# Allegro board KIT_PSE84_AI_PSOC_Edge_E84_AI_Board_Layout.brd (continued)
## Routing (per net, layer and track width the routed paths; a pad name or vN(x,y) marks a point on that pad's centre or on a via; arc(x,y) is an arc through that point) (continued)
AMIC2_CTB_REF: length 34.9
  TOP w0.089: v1(29.15,31.35) U1.J14
  L04_SIG2 w0.089: 31.17,31.71 29.51,31.71 v1(29.15,31.35)
  L04_SIG2 w0.157: 31.17,31.71 31.73,32.28 31.73,32.55 32.39,33.21 32.39,40.98 31.08,42.29 31.08,49.07 31.06,49.09 31.06,49.16 30.12,50.1 30.12,50.11 28.57,51.66 27.58,51.66 27.44,51.79 21.26,51.79 v2(20.4,50.93)
  BOTTOM w0.15: v2(20.4,50.93) 20.68,51.21 21.05,51.21 21.3,51.47 R228.1
AMIC_1V8: length 44
  TOP w0.229: v3(32.64,51.49) 32.94,51.79 C126.1 ; R224.2 R124.2 4.56,53.09 4.56,53.08 C118.1 4.17,54.42 4.18,54.43 v3(4.18,54.9)
  L03_SIG1 w0.229: v3(23.5,52.71) 22.73,51.94 21.03,51.94 20.85,51.77 13.89,51.77 12.65,53.01 v3(12.65,54.51)
  L04_SIG2 w0.229: v3(12.65,54.51) 11.52,54.51 11.12,54.9 v3(4.18,54.9) ; v3(32.64,51.49) 30.84,53.29 24.08,53.29 v3(23.5,52.71)
  BOTTOM w0.229: v3(12.65,54.51) 12.65,52.02 11.45,50.82 R125.1 ; v3(32.64,51.49) 32.33,51.8 U9.2 ; v3(23.5,52.71) 23.5,52.56 23.72,52.33 R134.1 ; U10.2 v3(4.18,54.9)
BOOT: length 36.6
  TOP w0.15: U1.N8 25.2,28.81 v1(25.2,28.79)
  L04_SIG2 w0.089: 30.28,39.29 30.86,38.71 31.17,38.71 ; 31.17,32.77 30.33,31.93 29.47,31.93 29.25,31.71 29.25,31.71 29.24,31.7 28.96,31.7 28.79,31.54 28.79,31.25 28.6,31.06 26.39,31.06 26.2,30.87 26.2,30.87 26.18,30.85 26.18,30.62 25.97,30.4 25.73,30.4 25.54,30.21 25.54,29.62 25.53,29.61 25.53,29.12 v1(25.2,28.79)
  L04_SIG2 w0.157: 30.28,39.29 30.04,39.53 30.04,45.91 v2(30.33,46.2) ; 31.17,32.77 31.42,33.02 31.57,33.02 32.13,33.59 32.13,38.31 31.73,38.71 31.17,38.71
  BOTTOM w0.15: R189.1 22.55,41.8 24.46,43.71 25.48,43.71 25.86,44.1 25.86,45.62 26.92,46.69 29.84,46.69 v2(30.33,46.2)
BT_DEV_WAKE: length 19
  TOP w0.15: v1(30.19,35.18) 29.66,35.18 U1.D15 ; U25.40 27.32,50.46 v2(27.3,50.47)
  L03_SIG1 w0.089: v1(30.19,35.18) 30.44,35.43 30.51,35.5 30.51,36.58 28.66,38.42 28.66,39.41
  L03_SIG1 w0.157: v2(27.3,50.47) 27.3,43.51 28.66,42.16 28.66,39.41
  BOTTOM w0.15: R106.2 27.31,50.04 27.3,50.04 v2(27.3,50.47)
BT_HOST_WAKE: length 22.4
  TOP w0.15: U25.41 26.82,50.26 v2(26.6,50.48) ; U1.D14 v1(29.12,35.29)
  L03_SIG1 w0.089: v1(29.12,35.29) 29.58,35.29 30.02,34.84 30.55,34.84 30.71,35 30.71,36.66 28.98,38.39 28.98,39.29
  L03_SIG1 w0.157: v2(26.6,50.48) 27.03,50.9 27.53,50.9 27.97,50.47 27.97,43.41 28.98,42.39 28.98,39.29
  BOTTOM w0.15: R107.2 27.2,51.08 v2(26.6,50.48)
BT_REG_ON: length 22.7
  TOP w0.15: U1.E14 v1(29.12,34.64) ; U25.8 20.84,45.69 20.72,45.8 R105.2 20,45.8 19.8,46 v2(19.48,46)
  L04_SIG2 w0.089: v1(29.12,34.64) 29.49,35.01 29.49,36.41 28.79,37.1 28.79,37.55 27.36,38.99 27.36,39.29
  L04_SIG2 w0.157: v2(19.48,46) 21.06,46 21.46,46.41 26.05,46.41 27.36,45.1 27.36,39.29
BT_UART_CTS_MCU_RTS: length 20.9
  TOP w0.15: U25.48 23.32,50.24 v2(22.89,50.67) ; U1.A14 v1(29.12,37.24)
  L03_SIG1 w0.089: 27.86,39.29 27.86,38.86 29.12,37.61 v1(29.12,37.24)
  L03_SIG1 w0.157: v2(22.89,50.67) 23.34,51.13 25.14,51.13 26.95,49.32 26.95,43.38 27.86,42.47 27.86,39.29
  BOTTOM w0.15: v2(22.89,50.67) 22.48,50.67 22.14,50.33 TP55.1
BT_UART_RTS_MCU_CTS: length 21.8
  TOP w0.15: U1.C15 30.02,35.61 v1(30.08,35.68) ; U25.47 23.82,50.52 23.67,50.67 v2(23.62,50.67)
  L04_SIG2 w0.089: 28.73,39.29 28.73,38.43 30.4,36.75 30.4,36 v1(30.08,35.68)
  L04_SIG2 w0.157: 28.73,39.29 28.73,42.01 28.07,42.67 28.07,48.34 26.9,49.51 24.79,49.51 v2(23.62,50.67)
  BOTTOM w0.15: TP56.1 23.39,50.45 v2(23.62,50.67)
BT_UART_RX_MCU_TX: length 17.9
  TOP w0.15: U1.A13 v1(28.47,37.24) ; U25.45 24.82,50.45 24.92,50.55 24.92,50.62 v2(24.94,50.65)
  L03_SIG1 w0.089: v1(28.47,37.24) 28.47,37.85 27.53,38.79 27.53,39.29
  L03_SIG1 w0.157: 27.53,39.29 27.53,42.04 25.68,43.89 25.68,49.91 v2(24.94,50.65)
  BOTTOM w0.15: v2(24.94,50.65) 25.55,50.65 25.91,50.29 TP53.1
BT_UART_TX_MCU_RX: length 20.7
  TOP w0.15: v2(24.32,50.7) U25.46 ; v1(30.02,36.53) 29.71,36.53 U1.B15
  L03_SIG1 w0.089: 27.2,39.29 27.2,38.63 27.49,38.34 27.49,37.1 27.68,36.91 27.99,36.91 28.14,36.75 28.14,36.45 28.33,36.26 29.76,36.26 v1(30.02,36.53)
  L03_SIG1 w0.157: v2(24.32,50.7) 24.32,44.54 27.2,41.66 27.2,39.29
  BOTTOM w0.15: v2(24.32,50.7) 24.65,50.37 TP54.1
DISP_VDD_3V3:
  vias: v3(16.99,57.71) v3(17.98,57.68)
DSI_CLK_N: length 37
  TOP w0.102: J10.11 9.37,56.62 9.74,56.99 9.74,59.71 v2(9.49,59.97)
  L03_SIG1 w0.102: v2(9.49,59.97) 9.73,59.73 9.73,58.68 8.51,57.45 8.51,57.08 8.83,56.75 8.83,56.61 8.69,56.46 8.55,56.46 8.22,56.79 7.84,56.79 7.53,56.48 7.53,56.1 7.86,55.77 7.86,55.63 7.72,55.49 7.57,55.49 7.24,55.81 6.87,55.81 6.58,55.52 6.58,52.23 8.13,50.68 8.13,44.25 11.89,40.49 14.54,40.49 14.76,40.7 15.3,40.7 v2(15.46,40.54)
  BOTTOM w0.102: v2(15.46,40.54) 15.62,40.69 16.2,40.69 16.62,40.28 18.17,40.28 R66.1
DSI_CLK_P: length 36.9
  TOP w0.102: J10.10 10.37,56.63 10,57.01 10,59.71 v2(10.26,59.97)
  L03_SIG1 w0.102: v2(15.46,41.31) 15.46,41.09 15.36,40.99 14.64,40.99 14.42,40.77 12.01,40.77 8.41,44.37 8.41,50.8 6.86,52.35 6.86,55.41 6.98,55.53 7.13,55.53 7.46,55.21 7.83,55.21 8.14,55.51 8.14,55.89 7.81,56.22 7.81,56.36 7.96,56.51 8.1,56.51 8.43,56.18 8.81,56.18 9.12,56.49 9.12,56.87 8.79,57.19 8.79,57.34 10.01,58.56 10.01,59.73 v2(10.26,59.97)
  BOTTOM w0.102: R67.1 18.17,40.53 16.72,40.53 16.31,40.95 15.57,40.95 15.46,41.05 v2(15.46,41.31)
DSI_DATA0_N: length 36.9
  TOP w0.102: v2(12.49,58.32) 12.64,58.32 12.74,58.21 12.74,57.91 12.59,57.76 12.59,57.45 12.74,57.3 12.74,56.99 12.37,56.62 J10.8
  L03_SIG1 w0.102: v2(12.49,58.32) 12.69,58.32 12.79,58.42 12.79,59.02 12.68,59.13 11.63,59.13 11.07,58.57 11.07,57.21 9.09,55.23 9.09,49.48 9.27,49.3 9.27,49 9.09,48.82 9.09,48.39 9.27,48.21 9.27,47.91 9.09,47.73 9.09,47.42 9.27,47.24 9.27,46.94 9.09,46.75 9.09,46.1 9.27,45.92 9.27,45.62 9.09,45.44 9.09,44.65 11.12,42.62 13.5,42.62 14.05,42.08 14.05,41.4 14.15,41.3 v2(14.36,41.3)
  BOTTOM w0.102: v2(14.36,41.3) 14.17,41.3 14.07,41.2 14.07,37.74 14.34,37.47 14.91,37.47 15.37,37.92 16.82,37.92 17.69,37.05 17.98,37.05 18.14,37.22 R70.1
DSI_DATA0_P: length 36.9
  TOP w0.102: v2(13.26,58.32) 13,58.06 13,56.98 13.37,56.61 J10.7
  L03_SIG1 w0.102: v2(13.26,58.32) 13.08,58.5 13.08,59.14 12.8,59.41 11.52,59.41 10.79,58.69 10.79,57.33 8.81,55.35 8.81,44.53 11,42.34 13.39,42.34 13.76,41.96 13.76,41.48 v2(13.59,41.3)
  BOTTOM w0.102: R71.1 17.87,36.8 17.58,36.8 16.71,37.67 15.47,37.67 15.01,37.21 14.24,37.21 13.82,37.63 13.82,41.07 v2(13.59,41.3)
DSI_DATA1_N: length 37
  TOP w0.102: v2(6.49,58.9) 6.64,58.9 6.74,58.8 6.74,58.5 6.59,58.34 6.59,58.04 6.74,57.89 6.74,57.01 6.37,56.64 J10.14
  L03_SIG1 w0.102: v2(6.49,58.9) 6.7,58.9 6.8,59.01 6.8,59.44 6.63,59.61 5.86,59.61 5.61,59.36 5.61,52.07 7.7,49.99 7.7,49.48 7.88,49.3 7.88,49 7.7,48.82 7.7,48.37 7.88,48.18 7.88,47.88 7.7,47.7 7.7,47.37 7.88,47.19 7.88,46.89 7.7,46.71 7.7,46.26 7.88,46.08 7.88,45.77 7.75,45.64 7.75,43.99 10.24,41.5 10.24,40.5 12.44,38.3 14.38,38.3 14.48,38.41 v2(14.48,38.64)
  BOTTOM w0.102: R68.1 18.17,38.8 17.69,38.8 17.27,38.38 15.18,38.38 15.1,38.3 14.58,38.3 14.48,38.41 v2(14.48,38.64)
DSI_DATA1_P: length 37
  TOP w0.102: v2(7.26,58.9) 7,58.65 7,56.99 7.37,56.61 J10.13
  L03_SIG1 w0.102: v2(7.26,58.9) 7.09,59.07 7.09,59.55 6.75,59.89 5.75,59.89 5.33,59.48 5.33,51.95 7.41,49.87 7.41,45.81 7.47,45.76 7.47,43.88 9.96,41.39 9.96,40.39 12.32,38.02 14.33,38.02 v2(14.48,37.87)
  BOTTOM w0.102: v2(14.48,37.87) 14.66,38.05 15.2,38.05 15.28,38.13 17.38,38.13 17.79,38.54 18.17,38.54 R69.1
ECO_IN: length 9.8
  TOP w0.15: v1(23.28,36.59) 23.34,36.53 23.34,36.52 U1.B6 ; v2(21.71,38.9) 21.11,38.9 20.72,39.3 20.72,39.46 20.12,40.06 20.12,40.1 ; 20.12,40.1 20.88,40.1 21.4,39.58 Y1.1 ; 20.12,40.1 C55.1
  L03_SIG1 w0.089: 24.28,37.14 24.24,37.11 24.24,37.1 24.05,36.91 23.6,36.91 23.52,36.84 23.52,36.83 v1(23.28,36.59)
  L03_SIG1 w0.157: 24.28,37.14 24.28,38.53 23.63,39.19 22,39.19 v2(21.71,38.9)
ECO_OUT: length 9.2
  TOP w0.15: v2(24.66,40.44) 24.6,40.38 C56.1 23.75,40.38 23.55,40.58 Y1.3 ; U1.F8 v1(25.22,33.99)
  L03_SIG1 w0.157: v1(25.22,33.99) 24.59,34.62 24.59,39.96 24.66,40.03 v2(24.66,40.44)
EXT_CLK: length 7.2
  TOP w0.15: U1.P4 21.94,28.11 v1(21.93,28.11)
  L03_SIG1 w0.089: v2(19.66,30.38) 19.66,30.38 20.14,29.9 20.14,29.39 20.47,29.06 21.13,29.06 21.18,29.11 21.45,29.11 21.64,28.92 21.64,28.47 21.69,28.43 21.69,28.35 v1(21.93,28.11)
  BOTTOM w0.15: v2(19.66,30.38) 19.66,32.32 19.34,32.65 R218.2
I2C_SCL_1V8: length 151.8
  TOP w0.089: U1.H7 24.53,32.07 v1(24.54,32.07) ; U18.13 19.1,20.96
  TOP w0.15: U6.4 35,18.99 v2(35.26,18.74) ; 19.1,20.96 19.1,20.8 18.75,20.46 18.75,20.44 18.5,20.19 R32.1 17.79,20.19 17.69,20.29 v2(16.98,20.29) ; v2(35.26,14.86) 35.2,14.86 34.61,15.45 34.51,15.45 U22.2
  L03_SIG1 w0.157: v2(35.26,14.86) 34.76,15.35 33.93,15.35 32.26,17.02 32.26,18.34 32.61,18.69 34.8,18.69 34.85,18.74 v2(35.26,18.74) ; v2(23.65,23.88) 23.22,23.45 23.22,13.94 22.36,13.08 22.36,13.08 20.56,11.28 19.9,11.28 19.9,11.28 19.2,11.28 18.19,12.29 17.35,12.29 16.64,13 15.87,13 15.44,12.58 8.46,12.58 v2(7.92,13.11) 8.21,13.4 8.34,13.4 9.54,14.6 9.54,15.52 10.06,16.03 10.06,19.98 10.89,20.8 15.88,20.8 16.39,20.29 v2(16.98,20.29) ; v2(10.03,24.45) 10.03,25.59 8.28,27.33 8.28,30.68 7.95,31.02 6.89,31.02 5.79,29.92 3.71,29.92 3.07,30.56 3.07,36.88 3.48,37.29 4.37,37.29 5.16,38.08 5.16,39.24 4.6,39.8 3.58,39.8 3.05,40.34 3.05,44.58 v2(3.71,45.24)
  L04_SIG2 w0.089: 24.64,27.82 24.64,30.65 24.91,30.92 24.91,31.7 v1(24.54,32.07)
  L04_SIG2 w0.102: 24.64,27.82 24.64,26.7 23.92,25.98 23.92,24.15 v2(23.65,23.88)
  L04_SIG2 w0.157: v2(35.26,18.74) 34.83,19.16 34.83,19.8 33.72,20.92 31.79,20.92 31.44,21.26 30.28,21.26 29.9,20.88 29.9,20.6 29.69,20.39 29.41,20.39 25.34,16.33 19.4,16.33 18.76,16.97 15.6,16.97 15.29,16.66 14.14,16.66 12.32,14.83 9.93,14.83 9.41,15.36 8.39,15.36 8.07,15.68 6.31,15.68 6.07,15.44 6.07,14.18 7.14,13.11 v2(7.92,13.11)
  BOTTOM w0.15: U28.10 10.14,24.66 10.06,24.57 10.06,24.49 v2(10.03,24.45) 10.03,24.09 11,23.12 13.46,23.12 14.1,22.48 14.1,21.29 15.09,20.29 v2(16.98,20.29) 16.98,19.88 17.02,19.85 17.02,19.84 17.88,18.97 19.41,18.97 19.74,18.64 U2.38 ; v2(3.71,45.24) 3.71,45.64 4.29,46.23 5.77,46.23 5.8,46.2 5.88,46.2 6.2,45.87 R223.2
I2C_SCL_3V3: length 105.5
  TOP w0.15: J14.17 3.1,24.39 3.1,29.08 3.71,29.69 4.6,29.69 5.21,30.3 5.21,44.82 4.42,45.6 4.42,47.27 5.13,47.98 5.13,48.68 10.53,54.08 14.83,54.08 15.37,54.62 J10.5 15.37,57.27 15.37,57.28 v2(15.37,57.71) ; v1(25.87,29.47) 25.84,29.47 U1.M9
  L03_SIG1 w0.157: v2(15.37,57.71) 15.9,57.18 20.13,57.18 21.31,56.01 v2(21.71,56.01)
  L04_SIG2 w0.089: 31.17,31.12 30.94,31.12 30.15,30.33 29.78,30.33 29.68,30.42 28.98,30.42 28.97,30.41 27.32,30.41 27.3,30.4 27.01,30.4 27,30.39 26.41,30.39 26.19,30.17 26.19,29.79 26.12,29.71 v1(25.87,29.47)
  L04_SIG2 w0.157: 31.17,31.12 31.99,31.94 31.99,32.44 32.65,33.1 32.65,41.09 31.34,42.4 31.34,49.18 31.32,49.2 31.32,49.26 30.38,50.21 30.38,50.22 28.37,52.22 22.67,52.22 22.05,52.85 22.05,55.67 v2(21.71,56.01)
  BOTTOM w0.15: v2(21.71,56.01) 21.31,55.6 20.27,55.6 20.12,55.75 R207.1 20.12,57.26 20.65,57.79 J7.4 ; v2(15.37,57.71) 15.37,56.97 13.97,55.58 9.32,55.58 8.43,54.69 J16.2
I2C_SDA_1V8: length 147.4
  TOP w0.089: U18.14 19.6,20.96
  TOP w0.15: v1(24.59,31.4) 24.59,31.4 U1.J8 ; 19.6,20.96 19.6,20.73 19.42,20.55 19.38,20.55 19.25,20.42 R31.1 19.67,20.19 20.61,19.25 v2(21.02,19.25) ; U22.1 34.51,14.65 34.83,14.65 v2(35.23,14.25) ; v2(35.24,19.39) 34.98,19.64 U6.3 ; v2(6.4,40.62) 5.61,41.4 5.61,44.77 4.73,45.65 4.73,46.33 v2(5.21,46.81)
  L03_SIG1 w0.089: 21.47,32.98 22.26,32.98 22.41,32.83 22.83,32.83 22.87,32.88 22.87,32.88 23.11,33.11 23.39,33.11 23.62,32.88 23.62,32.56 23.56,32.5 23.56,31.89 23.75,31.71 24.28,31.71 v1(24.59,31.4) ; v2(15.98,45.31) 15.98,45.31
  L03_SIG1 w0.152: 15.98,45.31 16.03,45.31 16.39,44.96 16.54,44.96 18.71,42.79 18.71,35.44 21.17,32.98 21.47,32.98
  L03_SIG1 w0.157: v2(8.86,13.18) 9.8,14.12 9.8,15.41 11.51,17.11 11.51,19.74 12.24,20.47 15.82,20.47 16.42,19.88 17.12,19.88 17.17,19.92 20.34,19.92 v2(21.02,19.25) ; v2(35.23,14.25) 34.54,14.94 32.82,14.94 31.8,15.95 31.8,18.95 32.33,19.48 33.34,19.48 33.82,19 34.86,19 v2(35.24,19.39) ; v2(6.4,40.62) 6.4,33.07 6.93,32.54 7.59,32.54 9.45,30.68 9.45,27.36 10.51,26.29 v2(10.51,24.18)
  L04_SIG2 w0.157: v2(8.86,13.18) 8.26,12.57 7.16,12.57 5.81,13.93 5.81,15.54 6.2,15.93 8.25,15.93 8.53,15.65 10.31,15.65 10.59,15.37 11.77,15.37 13.52,17.12 14.63,17.12 14.89,17.38 15.61,17.38 15.76,17.23 25.71,17.23 28.62,20.14 28.62,20.83 28.98,21.18 29.83,21.18 30.17,21.52 31.55,21.52 31.89,21.18 34.04,21.18 35.24,19.98 v2(35.24,19.39)
  BOTTOM w0.15: v2(15.98,45.31) 15.37,45.31 15.06,45.01 15.06,44.1 12.7,41.73 7.52,41.73 v2(6.4,40.62) ; R220.2 5.46,46.91 5.36,46.81 v2(5.21,46.81) ; v2(21.02,19.25) 21.03,19.24 21.03,19.19 20.88,19.04 U2.39 19.72,19.04 19.69,19.08 19.68,19.08 19.43,19.33 17.91,19.33 17.39,19.85 17.39,20.46 17.15,20.69 15.12,20.69 14.38,21.44 14.38,22.79 13.79,23.37 11.32,23.37 v2(10.51,24.18) 10.59,24.26 10.59,24.38 10.64,24.43 U28.9
I2C_SDA_3V3: length 101.7
  TOP w0.15: v1(25.86,27.53) 25.82,27.53 U1.R9 ; v2(16.32,57.75) 16.32,57.34 16.37,57.29 J10.4 16.37,55.2 15,53.83 10.77,53.83 5.71,48.77 5.71,46.41 v2(5.13,45.82)
  L03_SIG1 w0.157: v2(21.59,55.17) 22,55.17 22.2,55.37 22.2,56.34 20.32,58.22 16.79,58.22 v2(16.32,57.75)
  L04_SIG2 w0.089: v1(25.86,27.53) 25.98,27.53 26.33,27.19 26.33,26.87 25.96,26.49 25.96,25.66
  L04_SIG2 w0.102: 25.3,23.77 25.3,24.03 25.96,24.69 25.96,25.66
  L04_SIG2 w0.157: v2(4.67,19.38) 5.8,18.25 6.2,18.25 6.2,18.25 11.24,18.25 11.89,18.9 12.98,18.9 14.21,20.13 16.18,20.13 16.83,19.49 19.72,19.49 20.33,18.87 21.56,18.87 23.19,20.5 23.19,21.08 24.63,22.52 24.63,23.11 25.3,23.77
  BOTTOM w0.15: v2(5.13,45.82) 5.61,45.34 5.61,40.49 4.93,39.8 3.56,39.8 2.92,39.17 2.92,24.71 J14.18 3.16,21.78 3.16,20.43 4.22,19.38 v2(4.67,19.38) ; J16.4 10.97,54.69 11.53,55.25 14.22,55.25 16.32,57.34 v2(16.32,57.75) ; J7.3 19.65,57.19 19.47,57.02 R206.1 19.47,55.61 19.91,55.17 v2(21.59,55.17)
I2S_TX_FSYNC: length 32.5
  TOP w0.15: U1.E5 22.63,34.62 v1(22.61,34.62)
  L03_SIG1 w0.089: v1(22.61,34.62) 22.44,34.78 22.41,34.78 22.23,34.96 21.83,34.96 21.64,35.15 21.64,35.42 21.63,35.43 21.63,36.16 21.5,36.29 20.83,36.29 20.61,36.07 19.9,36.07
  L03_SIG1 w0.157: v2(20.31,37.63) 19.93,37.63 19.59,37.28 19.59,36.38 19.9,36.07
  L04_SIG2 w0.089: v2(20.31,37.63) 19.69,37.01 19.25,37.01 18.72,36.48
  L04_SIG2 w0.157: 18.72,36.48 16.66,34.42 16.3,34.42 14.83,32.94 14.83,32.64 14.32,32.13 12.52,32.13 10.8,30.41 10.8,24.47 10.92,24.35 10.92,23.62 11.1,23.45 12.69,23.45 12.9,23.66 v2(12.9,24.33)
  BOTTOM w0.15: U28.6 11.87,26.78 12.02,26.63 12.02,25.37 12.9,24.49 v2(12.9,24.33)
I2S_TX_MCK: length 32.5
  TOP w0.15: U1.D4 v1(21.97,35.29)
  L04_SIG2 w0.089: 20.55,35.61 21.45,35.61 21.47,35.6 21.66,35.6 v1(21.97,35.29)
  L04_SIG2 w0.157: v2(12.43,24.04) 11.8,24.04 11.63,24.21 11.63,24.66 11.48,24.82 11.44,24.82 11.28,24.98 11.28,25.29 11.44,25.45 11.86,25.45 12.02,25.61 12.02,25.85 11.78,26.08 11.34,26.08 11.18,26.24 11.18,26.55 11.34,26.71 11.83,26.71 12.12,26.99 12.12,28.15 11.42,28.85 11.42,29.1 11.61,29.28 11.9,29.28 12.52,28.67 12.74,28.67 13.14,29.06 13.14,29.28 12.21,30.21 12.21,30.43 12.43,30.66 12.66,30.66 13.58,29.73 13.8,29.73 14.92,30.84 15.94,30.84 16.18,31.09 16.18,31.5 16.96,32.28 16.96,32.5 16.72,32.75 16.72,32.97 16.94,33.2 17.16,33.2 17.43,32.92 17.73,32.92 17.96,33.14 17.96,33.37 17.54,33.78 17.54,34 17.74,34.2 17.96,34.2 18.35,33.81 18.62,33.81 19.58,34.77 19.58,34.99 19.04,35.53 19.04,35.76 19.2,35.92 19.42,35.92 19.96,35.38 20.19,35.38 20.42,35.61 20.55,35.61
  BOTTOM w0.15: v2(12.43,24.04) 12.02,24.04 12.01,24.05 11.47,24.05 11.23,24.29 11.23,25.72 U28.8
I2S_TX_SCK: length 32.5
  TOP w0.089: v1(23.95,30.74) 23.95,30.77 U1.K7
  L04_SIG2 w0.089: 18.72,31.3 18.86,31.44 19.09,31.44 19.26,31.26 19.26,31.16 19.46,30.96 19.96,30.96 20.21,30.71 20.21,29.93 20.37,29.77 20.69,29.77 20.84,29.93 20.84,30.8 21.01,30.96 22.94,30.96 23.01,31.04 23.65,31.04 v1(23.95,30.74)
  L04_SIG2 w0.157: 18.72,31.3 18.63,31.2 18.63,30.42 17.78,29.57 16.49,29.57 15.83,28.91 15.57,28.91 15.14,28.47 15.14,27.89 15.55,27.48 16.71,27.48 16.97,27.23 16.97,26.73 16.81,26.57 16.53,26.57 16.37,26.41 16.37,23.9 16.14,23.67 14.88,23.67 14.57,23.98 14.57,25.55 14.72,25.7 14.96,25.7 15.11,25.86 15.11,26.15 14.93,26.33 14.62,26.33 14.44,26.52 14.44,27.07 14.28,27.23 13.97,27.23 13.81,27.07 13.81,24.92 13.63,24.74 12.38,24.74 v2(12.22,24.58)
  BOTTOM w0.15: U28.7 11.47,26.28 11.76,25.99 11.76,25.96 11.77,25.95 11.77,25.03 11.93,24.87 11.93,24.86 v2(12.22,24.58)
I2S_TX_SD: length 32.6
  TOP w0.15: U1.E4 v1(21.97,34.64)
  L04_SIG2 w0.089: v1(21.97,34.64) 21.64,34.96 20.84,34.96 20.84,34.96
  L04_SIG2 w0.157: 20.84,34.96 20.68,34.96 19.99,34.26 19.99,34.04 20.91,33.12 20.91,32.95 20.62,32.67 20.42,32.67 19.4,33.68 19.18,33.68 19.03,33.53 19.03,33.22 20.47,31.78 20.47,31.45 20.31,31.29 19.97,31.29 18.53,32.73 18.31,32.73 18.08,32.5 18.08,31.79 17.9,31.6 17.68,31.6 17.3,31.98 17.07,31.98 16.85,31.76 16.85,31.54 17.23,31.16 17.23,30.93 16.81,30.51 16.81,30.25 16.58,30.03 16.36,30.03 16.1,30.29 15.88,30.29 15.4,29.82 15.18,29.82 14.83,30.17 14.61,30.17 14.39,29.94 14.39,29.72 15.03,29.08 15.03,28.86 14.82,28.65 14.57,28.65 13.94,29.28 13.72,29.28 13.49,29.05 13.49,28.83 14.12,28.2 14.12,27.98 13.9,27.76 13.68,27.76 13.05,28.38 12.83,28.38 12.48,28.04 12.48,27.61 12.64,27.45 12.92,27.45 13.08,27.29 13.08,26.98 12.92,26.82 12.64,26.82 12.48,26.66 v2(12.48,25.58)
  BOTTOM w0.15: v2(12.48,25.58) 12.48,25.66 12.29,25.85 12.29,26.8 11.81,27.28 U28.5
I3C_SCL: length 26.5
  TOP w0.15: U1.M4 21.97,29.44 21.92,29.44 v1(21.92,29.44)
  L03_SIG1 w0.089: 20.93,30.39 20.93,29.9 21.07,29.76 21.6,29.76 v1(21.92,29.44)
  L03_SIG1 w0.157: 20.93,30.39 16.74,34.58 16.74,37.24 15.38,38.6 15.38,39.51 15.89,40.02 15.89,41.46 14.14,43.21 11.05,43.21 10.1,44.16 10.1,44.87 v2(9.81,45.15)
  BOTTOM w0.15: v2(9.81,45.15) 9.81,45.9 TP71.1 9.25,45.9 9.15,45.8 R205.2 R222.2
I3C_SDA: length 27.6
  TOP w0.15: U1.L6 v1(23.27,30.09)
  L03_SIG1 w0.089: v1(23.27,30.09) 23.27,30.1 22.61,30.76 21.44,30.76 20.79,31.41 20.79,31.71
  L03_SIG1 w0.157: 20.79,31.71 20.26,32.24 19.96,32.24 18.63,33.57 18.61,33.57 17.29,34.89 17.29,38.33 16.23,39.39 16.23,41.5 14.22,43.51 11.11,43.51 10.36,44.26 v2(10.36,45.21)
  BOTTOM w0.15: v2(10.36,45.21) 10.36,46.48 TP72.1 9.58,47.04 9.45,46.91 R204.2 R221.2
IMU_INT1: length 11.9
  TOP w0.15: U1.L5 22.61,30.07 v1(22.61,30.05) ; v2(22.45,23.87) 21.82,23.87 20.92,22.98 U18.4
  L04_SIG2 w0.089: v1(22.61,30.05) 22.9,29.76 23.41,29.76 23.59,29.57 23.59,29.3 23.78,29.11 24.12,29.11 24.27,28.96 24.27,28.37
  L04_SIG2 w0.102: 24.27,28.37 24.27,27.91 24.16,27.8 23.05,27.8 22.78,27.53 22.78,25.77 22.99,25.56 22.99,24.41 v2(22.45,23.87)
IMU_INT2: length 8.6
  TOP w0.15: U18.9 18.39,22.48 18.42,22.51 18.51,22.51 v2(18.56,22.55) ; U1.P5 v1(22.62,28.14)
  L03_SIG1 w0.089: v1(22.62,28.14) 22.62,27.35 21.86,26.59
  L03_SIG1 w0.157: 21.86,26.59 20.96,25.69 20.96,24.72 20.88,24.64 20.88,24.63 19.19,22.94 19.06,22.94 19.06,22.94 18.94,22.94 v2(18.56,22.55)
JTAG_SEL: length 1.7
  TOP w0.15: U25.57 22.36,45.69 v2(22.04,46)
  BOTTOM w0.15: v2(22.04,46) 22.45,46 22.58,46.13 R110.2
KP_USB_DM: length 20.4
  TOP w0.114: J1.A7 25.91,5.97 25.81,5.86 25.81,5.3 v2(26.03,5.07) ; J1.B7 v2(24.91,7.74)
  L03_SIG1 w0.114: 25.42,7.74 25.54,7.86 25.54,8.44 27.78,10.69 27.78,12.53 v2(27.53,12.78) ; 25.42,7.74 25.54,7.63 25.54,6.89 24.65,6 24.65,5.49 24.46,5.3 24.46,4.36 24.72,4.1 25.53,4.1 25.83,4.4 25.83,4.87 v2(26.03,5.07) ; 25.42,7.74 v2(24.91,7.74)
  BOTTOM w0.114: U19.1 25.29,7.05 25.54,7.3 25.54,7.61 25.43,7.72 24.93,7.72 v2(24.91,7.74) ; R28.1 26.14,14.04 26.14,13.33 26.39,13.08 27.29,13.08 27.37,13.16 27.65,13.16 27.79,13.03 v2(27.53,12.78)
KP_USB_DP: length 20.3
  TOP w0.114: J1.B6 v2(26.41,7.74) ; J1.A6 25.41,5.97 25.58,5.8 25.58,5.21 25.43,5.07 v2(25.29,5.07)
  L03_SIG1 w0.114: v2(25.29,5.07) 25.47,5.07 25.58,4.96 25.58,4.5 25.42,4.34 24.82,4.34 24.71,4.46 24.71,5.2 24.89,5.39 24.89,5.9 25.12,6.12 25.28,6.12 25.38,6.01 25.55,6.01 25.71,6.18 25.71,6.34 25.6,6.44 25.6,6.6 25.79,6.79 25.79,7.63 25.9,7.74 ; 25.9,7.74 25.79,7.86 25.79,8.34 28.03,10.58 28.03,12.53 v2(28.27,12.78) ; 25.9,7.74 v2(26.41,7.74)
  BOTTOM w0.114: v2(28.27,12.78) 28.02,13.03 28.02,13.12 27.75,13.39 27.28,13.39 27.2,13.31 26.49,13.31 26.37,13.42 26.37,14.04 R26.1 ; v2(26.41,7.74) 26.38,7.77 25.88,7.77 25.77,7.66 25.77,7.33 U19.2
KP_VBUS:
  vias: v3(22.74,7.93) v3(23.27,7.63) v3(23.67,3.94) v3(23.67,2.67) v3(28.12,8.36) v3(28.07,7.68)
LPO_OUT_2FY: length 1.8
  TOP w0.15: R182.2 28.71,45.45 28.45,45.19 U25.30
MAG_INT: length 5.9
  TOP w0.15: U20.A1 18.42,27.66 19.97,27.66 20.63,27 22.13,27 U1.R5
MCU_UART_RX_KP3_TX: length 51.8
  TOP w0.15: U1.R2 v1(20.67,27.49)
  L03_SIG1 w0.089: v1(20.67,27.49) 20.67,27.14 20.02,26.49
  L03_SIG1 w0.102: 20.02,26.49 19.86,26.33
  L03_SIG1 w0.157: v2(6.99,14.94) 8.53,16.49 8.97,16.49 9.7,17.22 9.7,20.44 12.25,22.99 15.46,22.99 16.76,24.28 19.43,24.28 20.11,24.96 20.11,25.65 19.86,25.89 19.86,26.33
  L04_SIG2 w0.157: v2(28.97,13.62) 28.97,14.02 28.96,14.04 28.96,14.17 27.66,15.47 19.88,15.47 18.66,16.69 16.11,16.69 15.29,15.88 14.02,15.88 12.67,14.52 7.4,14.52 v2(6.99,14.94)
  BOTTOM w0.15: U2.20 26.65,16.12 27.4,15.37 28.24,15.37 28.42,15.19 28.42,14.51 28.96,13.97 28.96,13.67 28.97,13.65 v2(28.97,13.62)
MCU_UART_TX_KP3_RX: length 51.7
  TOP w0.15: U1.P2 v1(20.67,28.14)
  L03_SIG1 w0.089: v1(20.67,28.14) 20.09,27.56 20.04,27.56 20.02,27.53 19.18,27.53 18.98,27.33 18.98,27.04 19.15,26.87 19.15,26.59
  L03_SIG1 w0.157: v2(6.48,15.27) 8.36,17.15 8.36,18.53 8.13,18.76 8.13,19.69 9.12,20.68 9.12,21.9 10.52,23.29 13.92,23.29 15.59,24.96 16.47,24.96 16.76,25.25 18.23,25.25 18.23,25.25 19.05,25.25 19.48,25.68 19.48,26.23 19.23,26.49 19.23,26.52 19.15,26.59
  L04_SIG2 w0.157: v2(6.48,15.27) 6.48,14.86 7.07,14.26 13.86,14.26 15.21,15.62 15.4,15.62 16.22,16.43 18.56,16.43 19.78,15.22 27,15.22 27.61,14.61 v2(27.61,13.89)
  BOTTOM w0.15: v2(27.61,13.89) 27.61,14.3 27.41,14.5 R29.1 27.09,15.18 27.09,15.28 26.25,16.12 U2.21
MCU_VDD_3V3: length 25.7
  TOP w0.15: U1.R10 26.51,27.5 v1(26.51,27.49) ; U1.B11 v1(27.17,36.59) ; U1.D10 v1(26.52,35.29)
  TOP w0.229: R197.1 25.03,24.94 C179.1 C180.1 26.31,24.94 26.57,25.19 26.57,26.94 26.51,27 v1(26.51,27.49)
  L05_PWR w0.089: 31.17,36.09 31.08,36.09 30.26,36.91 27.49,36.91 v1(27.17,36.59) U1.B11 26.84,35.61 v1(26.52,35.29) 26.84,34.96 27.3,34.96 27.49,34.77 27.49,34.5 27.3,34.31 27.08,34.31 27.08,34.31 27.03,34.31 26.8,34.07 26.8,32.77 26.22,32.19 26.22,30.89 26.19,30.87 26.19,29.3 26.38,29.11 27.41,29.11 27.5,29.02 27.5,28.01 27.3,27.81 27.28,27.81 27.28,27.81 26.83,27.81 v1(26.51,27.49)
  L05_PWR w0.229: v3(31.55,36.09) 31.17,36.09
  BOTTOM w0.229: v1(26.51,27.49) 26.51,27 26.52,26.99 26.52,26.7 26.56,26.65 R154.2 ; C139.1 31.12,36.4 31.42,36.09 v3(31.55,36.09)
MEMORY_RST: length 17.9
  TOP w0.15: v1(13.23,37.03) 12.93,37.03 U3.A4 ; v1(23.27,30.67) 23.26,30.68 23.26,30.75 U1.K5
  BOTTOM w0.15: v1(23.27,30.67) 22.89,30.67 22.67,30.46 21.01,30.46 20.27,29.72 19.4,29.72 19,30.11 19,30.65 18.01,31.65 18.01,34.24 17.83,34.42 17.83,36.27 17.58,36.52 R208.1 16.69,36.52 16.36,36.86 15.9,36.86 15.51,36.47 13.75,36.47 13.23,36.98 v1(13.23,37.03)
Net_4: length 0.5
  TOP w0.15: 25.54,33.66 25.57,33.66 v1(25.89,33.99)
P5LP1_2: length 13.8
  TOP w0.15: v2(29.16,18.89) 29.48,18.89 29.95,18.42 30.57,18.42 v2(30.9,18.08)
  BOTTOM w0.15: v2(29.16,18.89) 29,19.04 U2.13 ; v2(30.9,18.08) 30.9,17.46 31.11,17.25 31.11,15.92 30.86,15.68 30.86,14.6 31.06,14.4 31.06,12.82 31.41,12.47 SW3.1 SW3.2
P5LP1_4: length 16.4
  TOP w0.15: R30.2 31.79,5.68 31.55,5.92 v2(31.55,6.2)
  L03_SIG1 w0.157: v2(29.06,17.93) 28.22,17.09 28.22,15.62 30.53,13.31 30.53,11.76 31.9,10.39 31.9,9.05 31.9,9.05 31.9,7.65 32.5,7.05 32.5,6.73 32.26,6.49 31.84,6.49 v2(31.55,6.2)
  BOTTOM w0.15: U2.15 28.75,18.24 v2(29.06,17.93)
P5LP_SIO_VREF: length 2.5
  BOTTOM w0.15: R21.2 R22.2 19.2,23.25 19.8,22.64 U2.48
P5LP_SWCLK: length 2.5
  BOTTOM w0.15: TP19.1 29.78,18.89 29.22,19.44 U2.12
P5LP_SWDIO: length 3.5
  BOTTOM w0.15: TP20.1 30.87,19.33 30.28,19.91 29.09,19.91 29.02,19.84 U2.11
P5LP_VCCD: length 19
  L03_SIG1 w0.229: v3(22.35,13.69) 22.35,13.98 22.71,14.33 22.71,18.79 22.3,19.2 22.3,20.98 22.05,21.24 22.05,24.47 22.17,24.6 22.17,24.63 22.56,25.02 v3(22.56,25.49)
  BOTTOM w0.178: U2.26 24.25,16.02 23.83,15.6 C44.1 23.83,14.81 23.68,14.66 23.27,14.66 22.88,14.27 22.88,13.99 22.58,13.69 v3(22.35,13.69) ; v3(22.56,25.49) 22.56,25.81 22.84,26.09 C45.1 23.07,25.72 23.05,25.7 U2.57
P5LP_VDD: length 39
  TOP w0.229: R18.1 29.61,8.79 29.97,9.15 30.22,9.15 v3(30.23,9.14)
  L04_SIG2 w0.229: v3(17.1,21.87) 17.42,21.87 17.9,21.4 19.34,21.4 20.22,22.27 20.22,24.79 v3(19.71,25.3)
  BOTTOM w0.157: C46.1 20.79,26.43 21.01,26.65 21.49,26.65 21.77,26.93 23.06,26.93 23.17,27.04 23.34,27.04 23.47,27.16 v3(23.75,27.16)
  BOTTOM w0.178: U2.24 25.05,15.6 25.1,15.54 C40.1 C39.1 ; U2.59 23.85,25.4 24.08,25.63 24.08,25.82 24.32,26.07 C49.1 24.32,26.49 24.31,26.51 C48.1 24.06,27.15 23.77,27.15 v3(23.75,27.16) ; v3(29.43,25.74) 29.11,26.06 28.92,26.06 28.9,26.04 C51.1 C50.1 27.22,26.04 27.05,25.86 U2.67 ; U2.52 21.05,25.19 20.79,25.44 C46.1 ; v3(18.64,18.54) 18.2,18.54 18.17,18.52 18.16,18.52 17.98,18.34 C37.1 C38.1 19.18,17.98 19.72,17.44 U2.35 ; U2.44 19.33,21.04 19.18,21.2 C36.1 C35.1 18.02,21.54 17.68,21.87 v3(17.1,21.87) ; U2.17 29.09,17.44 29.28,17.26 C42.1 C41.1 29.62,15.86 29.61,15.85 v3(29.61,15.81)
  BOTTOM w0.229: R25.1 28.92,14.71 29.56,14.07 30.09,14.07 v3(30.42,14.4) ; v3(19.71,25.3) 20.08,25.68 C47.1 20.09,26.07 C46.1 ; v3(29.43,25.74) 29.46,25.71 TP16.1
  BOTTOM w0.254: v3(25.2,12.8) 25.2,13.29 25.33,13.41 25.33,14.13 25.1,14.35 C39.1
P5LP_XRES: length 3.8
  BOTTOM w0.15: TP18.1 30.95,21.4 30.95,20.57 30.59,20.2 29.07,20.2 29.03,20.24 U2.10
P11_1: length 37.4
  TOP w0.15: U1.E11 v1(27.17,34.64)
  L03_SIG1 w0.089: 26.34,39.29 26.31,39.27 26.31,37.49 26.19,37.37 26.19,37.1 26.39,36.91 26.65,36.91 26.84,36.72 26.84,34.96 v1(27.17,34.64)
  L03_SIG1 w0.157: v2(12.75,45.55) 12.75,47.11 14.07,48.43 19.1,48.43 21.69,45.85 21.69,44.71 22.94,43.46 24.36,43.46 26.34,41.48 26.34,39.29
  BOTTOM w0.15: TP70.1 11.54,43.94 12.75,45.14 v2(12.75,45.55) 13.03,45.84 13.03,47.75 13.71,48.43 U40.7
P11_1_IN_3V3: length 29.1
  BOTTOM w0.15: J14.13 5.07,29.4 5.07,38.64 5.91,39.48 5.91,40.76 7.21,42.06 12.6,42.06 14.81,44.27 14.81,44.98 14.81,44.99 14.81,45.11 15.26,45.57 15.66,45.57 15.81,45.72 16.15,45.72 16.39,45.96 16.39,48.33 16.28,48.43 U40.2
P16_0: length 59.9
  TOP w0.15: U1.M11 v1(27.17,29.44) ; J14.6 0.58,37.62 0.58,20.14 v2(1.58,19.14)
  L04_SIG2 w0.089: v1(27.17,29.44) 27.5,29.1 27.5,28.25 28.19,27.56 28.19,26.62 28.17,26.59
  L04_SIG2 w0.157: 28.17,26.59 28.09,26.51 28.09,25.25 27.5,24.67 27.5,24.17 27.83,23.84 27.83,23.54 27.71,23.43 27.71,20.77 24.68,17.75 15.98,17.75 15.48,18.24 13.87,18.24 12.73,17.1 11.23,17.1 10.84,16.7 3.51,16.7 1.58,18.62 v2(1.58,19.14)
P16_1: length 106
  TOP w0.15: v1(28.55,27.36) 28.55,27.4 U1.R13
  L03_SIG1 w0.089: 29.53,26.59 29.53,26.82 28.99,27.36 v1(28.55,27.36)
  L03_SIG1 w0.157: J14.5 2.72,40.01 2.72,41.81 2.31,42.22 0.91,42.22 0.59,41.89 0.59,9.96 3.28,7.27 3.28,5.26 5.34,3.2 6.02,3.2 8.64,0.59 27.3,0.59 31.46,4.75 33.75,4.75 34.67,5.67 34.67,8.97 34.24,9.4 34.24,9.7 33.84,10.11 33.84,10.13 32.13,11.83 32.13,13.29 30.58,14.83 30.25,14.83 30.02,15.07 30.02,18.9 29.63,19.29 29.63,19.65 30.15,20.17 30.56,20.17 30.94,20.55 30.94,21.12 30.48,21.58 30.48,23.53 30.26,23.75 30.26,25.87 29.53,26.59
P16_2: length 51.6
  TOP w0.15: U1.N11 v1(27.17,28.79)
  L04_SIG2 w0.089: v1(27.17,28.79) 26.84,28.46 26.38,28.46 26.19,28.27 26.19,28 26.38,27.81 26.64,27.81 26.83,27.62 26.83,26.92 26.19,26.27 26.19,24.08 26.12,24.01 26.12,23.46
  L04_SIG2 w0.157: J14.8 2.9,34.74 2.9,20.49 5.4,17.99 6.09,17.99 6.09,17.99 11.35,17.99 11.97,18.62 13.06,18.62 14.31,19.87 16.07,19.87 16.72,19.23 19.61,19.23 20.27,18.57 22.49,18.57 23.65,19.72 23.65,20.99 26.12,23.46
P16_3: length 64
  TOP w0.15: v1(27.15,30.06) 27.15,30.1 U1.L11
  L04_SIG2 w0.089: v1(27.15,30.06) 27.19,30.06 27.54,29.71 27.97,29.71 28.16,29.52 28.16,28.95 28.15,28.95 28.15,28.63 28.16,28.62 28.16,27.97 28.36,27.77 28.59,27.77 28.87,27.49 28.87,26.79 28.73,26.65 28.73,26.59
  L04_SIG2 w0.157: 28.73,26.59 28.52,26.39 28.52,24.6 28.17,24.25 28.17,20.78 24.88,17.49 15.87,17.49 15.38,17.98 14.01,17.98 12.87,16.84 11.34,16.84 10.94,16.44 2.79,16.44 0.59,18.64 0.59,36.68 0.99,37.09 3.1,37.09 J14.7
P16_4: length 50.1
  TOP w0.15: U1.P11 v1(27.17,28.14)
  L04_SIG2 w0.089: v1(27.17,28.14) 27.53,27.77 27.53,26.24
  L04_SIG2 w0.102: 27.53,26.24 27.1,25.81
  L04_SIG2 w0.157: J14.10 2.64,32.46 2.64,30.81 2.63,30.8 2.63,19.09 4.76,16.96 10.73,16.96 11.15,17.37 12.64,17.37 13.76,18.5 15.59,18.5 16.08,18 23.85,18 27.08,21.24 27.08,25.78 27.1,25.81
P16_5: length 95.6
  TOP w0.15: v1(26.54,30.06) U1.L10 ; J14.9 2.82,32.23 2.82,20.37 3.81,19.38 3.81,14.81 3.43,14.43 v2(1.04,14.43)
  L03_SIG1 w0.089: v1(26.54,30.06) 26.84,29.76 26.84,29.3 27.03,29.11 27.3,29.11 27.49,28.92 27.49,28.52 27.8,28.21 27.8,27.82 28.21,27.41 28.21,27.21 28.83,26.59
  L03_SIG1 w0.157: v2(1.04,14.43) 0.91,14.3 0.91,10.2 3.63,7.48 3.63,5.27 5.45,3.46 6.13,3.46 8.75,0.85 27.19,0.85 31.35,5 31.7,5 32.88,6.18 32.88,6.92 33.3,7.34 33.3,10.3 31.34,12.25 31.34,12.86 28.5,15.71 28.5,16.92 29.11,17.52 29.23,17.52 29.59,17.89 29.59,18.97 29.38,19.18 29.38,19.78 29.91,20.32 29.91,21.3 30.22,21.6 30.22,23.39 30,23.61 30,25.71 29.58,26.13 29.3,26.13 28.83,26.59
P16_6: length 45.8
  TOP w0.15: v2(3.23,19.31) 2.57,19.97 2.57,30 J14.12 ; U1.R11 v1(27.17,27.49)
  L04_SIG2 w0.089: 26.83,25.9 26.83,26.66 27.17,27 v1(27.17,27.49)
  L04_SIG2 w0.157: v2(3.23,19.31) 3.23,18.86 4.35,17.73 11.45,17.73 12.04,18.32 13.12,18.32 14.09,19.28 14.81,19.28 15.28,18.81 15.9,18.81 16.43,18.28 17.67,18.28 18.34,18.95 19.43,18.95 20.09,18.29 22.58,18.29 26.82,22.53 26.82,25.89 26.83,25.9
P16_7: length 43.6
  TOP w0.15: U1.M10 v1(26.52,29.44)
  L04_SIG2 w0.089: v1(26.52,29.44) 26.19,29.11 26.19,28.65 26,28.46 25.73,28.46 25.04,27.77 25.04,24.99 24.52,24.47 24.52,23.57
  L04_SIG2 w0.157: J14.11 3.16,30.03 3.16,22.95 4.9,21.21 4.9,19.99 4.9,19.99 4.9,19.73 6.12,18.51 6.3,18.51 6.31,18.51 11.13,18.51 12.05,19.43 12.05,20 12.53,20.47 16.21,20.47 16.77,19.91 19.66,19.91 19.96,19.61 21.68,19.61 22.1,20.03 22.1,21.08 24.52,23.5 24.52,23.57
P17_2: length 79.8
  TOP w0.15: U1.R8 24.89,27.34 v1(25.47,26.77)
  L03_SIG1 w0.089: 26.94,23.07 26.94,23.58 27.01,23.64 27.01,24.11 26.58,24.54 26.58,25.68 25.84,26.42 25.81,26.42 v1(25.47,26.77)
  L03_SIG1 w0.157: J14.15 2.88,24.67 2.88,19.83 2.55,19.5 2.55,10.17 4.78,7.94 4.78,5.6 5.82,4.56 6.54,4.56 8.38,2.72 11.76,2.72 12.8,3.76 15.51,3.76 16.28,2.99 17.06,2.99 17.78,3.71 21.9,3.71 23.68,1.93 26.75,1.93 29.26,4.45 29.26,7.31 29.06,7.51 29.06,8.11 29.64,8.69 29.64,10.61 28.78,11.47 28.78,12.85 28.44,13.19 27.34,13.19 27.08,12.93 27.08,12.45 26.8,12.18 26.41,12.18 26.02,12.56 26.02,18.06 26.94,18.98 26.94,23.07
P17_3: length 79.8
  TOP w0.15: U1.P9 v1(25.87,28.14)
  L03_SIG1 w0.089: v1(25.87,28.14) 26.18,27.82 26.18,27.35 26.52,27.02 26.52,26.59
  L03_SIG1 w0.157: J14.16 2.36,25.13 2.36,20.09 2.02,19.75 2.02,9.87 4.21,7.68 4.21,5.43 5.6,4.04 6.33,4.04 8.36,2.01 12.66,2.01 13.89,3.24 15.3,3.24 16.06,2.47 17.41,2.47 18.12,3.19 21.69,3.19 23.47,1.41 27.03,1.41 30.87,5.26 30.87,10.23 29.33,11.77 29.33,13.78 27.61,15.5 27.61,17.91 28.22,18.52 28.22,24.3 28.32,24.4 28.32,24.71 28.09,24.94 27.39,24.94 27.13,25.19 27.13,25.72 26.52,26.34 26.52,26.59
P17_4: length 81.8
  TOP w0.15: U1.P8 25.27,28.08 25.27,27.59 25.86,27 v1(26.01,27)
  L03_SIG1 w0.089: 26.86,25.5 26.86,25.67 26.29,26.24 26.29,26.72 v1(26.01,27)
  L03_SIG1 w0.157: 26.86,25.5 26.86,24.65 27.35,24.16 27.67,24.16 27.94,23.89 27.94,18.65 27.23,17.93 27.23,14.91 28.04,14.1 28.04,13.74 28.28,13.5 28.58,13.5 29.06,13.02 29.06,11.56 30.61,10.01 30.61,5.36 26.92,1.67 23.57,1.67 21.8,3.45 17.95,3.45 17.24,2.73 16.17,2.73 15.41,3.5 13.78,3.5 12.55,2.27 8.47,2.27 6.44,4.3 5.71,4.3 4.47,5.54 4.47,7.83 2.29,10 2.29,19.64 2.62,19.97 2.62,27.41 J14.14
P17_5: length 102.6
  TOP w0.15: U1.N9 v1(25.87,28.79)
  L03_SIG1 w0.089: 26.82,27.32 26.84,27.34 26.84,28.27 26.65,28.46 26.19,28.46 v1(25.87,28.79)
  L03_SIG1 w0.102: 27.37,26.04 27.25,26.16 27.03,26.16 26.82,26.37 26.82,27.32
  L03_SIG1 w0.157: v2(1,19.13) 1,15.67 1.76,14.91 1.76,9.72 3.95,7.53 3.95,5.33 5.55,3.72 6.24,3.72 8.82,1.14 12.34,1.14 14.18,2.98 14.85,2.98 16.38,1.45 16.89,1.45 18.37,2.93 21.58,2.93 23.36,1.15 27.13,1.15 31.13,5.15 31.13,10.68 30.2,11.61 30.2,13.27 27.91,15.56 27.91,17.78 28.48,18.34 28.48,24.19 28.58,24.29 28.58,24.84 27.37,26.04
  L04_SIG2 w0.157: J14.1 J14.3
  BOTTOM w0.15: J14.3 2.9,39.93 1.42,39.93 0.58,39.09 0.58,19.54 v2(1,19.13)
P17_7: length 89.6
  TOP w0.15: U1.L9 25.87,30.09 v1(25.87,30.08)
  L03_SIG1 w0.089: v1(25.87,30.08) 25.53,29.74 25.53,29.27 25.52,29.26 25.52,28.29 25.27,28.04 25.27,27.18 25.23,27.14 25.23,27.13 25.13,27.03 25.13,26.36 25.26,26.23 25.76,26.23 26.39,25.6 26.39,24.46 26.82,24.03 26.82,23.72 26.52,23.42 26.52,23.07
  L03_SIG1 w0.157: 26.52,23.07 26.52,18.93 25.7,18.11 25.7,12.57 25.4,12.27 25.4,9.7 24.13,8.43 22.61,8.43 22.28,8.1 21.76,8.1 21.43,7.77 21.42,7.77 16.9,3.25 16.38,3.25 15.62,4.01 12.62,4.01 11.61,3 8.47,3 6.65,4.82 5.92,4.82 5.26,5.48 5.26,7.64 5.57,7.94 5.57,8.26 5.16,8.67 4.47,8.67 2.81,10.32 2.81,19.4 3.16,19.75 3.16,23.6 5.07,25.51 5.07,26.39 2.72,28.74 2.72,39.05 1.58,40.19 J14.4
  L04_SIG2 w0.157: J14.2 J14.4
PDM_CLK: length 101.9
  TOP w0.15: v2(11.61,7.75) 11.66,7.79 R88.2 11.66,8.59 10.77,9.48 10.31,9.48 10.08,9.7 10.08,10.14 9.14,11.08 5.3,11.08 4.91,11.46 4.91,15.11 5.69,15.89 5.69,18.95 6.27,19.53 7.06,19.53 7.18,19.65 7.18,19.68 v2(7.47,19.97) ; U1.E7 24,34.55 24,34.56 23.98,34.58 23.98,34.62 v1(23.95,34.65)
  L03_SIG1 w0.089: 19.79,38.63 21.46,38.63 21.56,38.54 21.57,38.54 21.97,38.13 22.18,38.13 22.94,37.37 22.94,36.73 22.94,36.72 22.94,36.45 23.14,36.25 23.43,36.25 23.59,36.09 23.59,35.15 23.95,34.79 v1(23.95,34.65)
  L03_SIG1 w0.157: 19.79,38.63 19.25,39.17 19.25,43.08 17.9,44.43 17.9,45.2 17.33,45.77 13.9,45.77 v2(13.46,45.34) ; v2(11.61,7.75) 11.61,8.16 11.96,8.51 14.78,8.51 16.88,6.42 16.88,4.05 v2(16.59,3.76)
  L04_SIG2 w0.157: v2(16.59,3.76) 17.4,2.94 22.84,2.94 23.5,2.28 29.13,2.28 31.5,4.65 33.66,4.65 34.93,5.93 34.93,7.04 34.6,7.38 v2(34.6,9.55) ; v2(7.47,19.97) 7.81,20.31 7.81,25.43 8.09,25.7 8.09,31.2 8.38,31.5 8.38,32.44 8.86,32.92 8.86,32.94 10.54,34.62 10.54,37.92 12.9,40.29 12.9,41.15 13.46,41.71 v2(13.46,45.34)
  BOTTOM w0.15: v2(34.6,9.55) 34.89,9.84 34.89,10.3 34.59,10.59 R92.2
PDM_DATA: length 106.4
  TOP w0.15: R87.2 9.8,8.38 9.19,9 8.77,9 v2(8.48,8.71) 6.55,8.71 4.11,11.15 4.11,19.64 4.36,19.88 4.92,19.88 5.27,20.23 5.63,20.23 5.84,20.02 v2(6.88,20.02) ; U1.G6 v1(23.29,32.7)
  L03_SIG1 w0.157: v1(23.29,32.7) 23.01,32.43 22.51,32.43 22.24,32.7 20.96,32.7 18.21,35.46 18.21,42.27 17.04,43.44 15.7,43.44 15.14,43.99 12.7,43.99 v2(11.4,45.29)
  L04_SIG2 w0.157: v2(32.92,9.42) 33.86,8.48 33.86,7.75 34.62,6.99 34.62,5.98 33.57,4.93 31.41,4.93 29.02,2.54 24.34,2.54 23.68,3.2 18.64,3.2 17.68,4.17 15.64,4.17 14.96,3.48 10.24,3.48 8.34,5.38 8.34,7.7 8.48,7.85 v2(8.48,8.71) ; v2(11.4,45.29) 11.4,39.22 10.24,38.05 10.24,34.7 7.54,32.01 7.54,31.02 7.83,30.74 7.83,25.89 7.39,25.45 7.39,20.96 6.98,20.55 6.98,20.53 6.88,20.43 v2(6.88,20.02)
  BOTTOM w0.15: v2(32.92,9.42) 32.92,10.46 33.05,10.59 R91.2
PE84_RST_L: length 97.6
  TOP w0.15: v2(28.95,23.49) 28.39,23.49 27.77,24.11 27.25,24.11 26.62,23.47 25.33,23.47 25.28,23.42 24.16,23.42 23.32,22.58 23.32,22.02 22.28,20.98 22.28,19.56 21.4,18.68 20.23,18.68 19.91,19 18.41,19 17.67,18.26 17.23,18.26 16.79,18.7 16.79,19.28 16.15,19.92 15.74,19.92 15.39,19.57 14.03,19.57 12.85,18.39 10.87,18.39 10.29,17.81 8.69,17.81 7.7,18.8 7.7,19.58 7.93,19.81 7.93,23.38 8.3,23.75 10.68,23.75 11.01,24.08 R72.2 C58.1 11.01,24.97 10.52,25.45 SW2.2 SW2.1 ; J4.10 9.58,40.57 11.74,38.41 13.36,38.41 14.15,39.19 v2(14.55,39.19) ; U1.D8 v1(25.22,35.29)
  L03_SIG1 w0.089: 27.41,26.96 27.41,27.27 27.49,27.35 27.49,28.27 27.3,28.46 27.03,28.46 26.84,28.65 26.84,28.76 26.84,28.76 26.84,28.92 26.65,29.11 26.31,29.11 26.19,29.23 26.19,29.57 26.2,29.58 26.2,30.22 26.01,30.42 25.36,30.42 25.35,30.41 25.08,30.41 24.89,30.6 24.89,30.87 25.09,31.06 25.35,31.06 25.51,31.22 25.51,32.2 25.32,32.39 25.32,32.87 26.26,33.81 26.26,34.44 26.21,34.5 26.21,34.51 26.2,34.52 26.2,35.14 26.19,35.15 26.19,35.48 26.06,35.61 25.54,35.61 v1(25.22,35.29) 24.87,35.64 24.87,37.57 25.25,37.95
  L03_SIG1 w0.102: 27.84,26.53 27.41,26.96
  L03_SIG1 w0.157: 25.25,37.95 25.25,40.54 24.94,40.85 24.81,40.85 20.5,45.16 20.5,46.47 19.78,47.18 v2(17.75,47.18) ; v2(28.95,23.49) 28.95,24.1 28.98,24.12 28.98,25.01 27.84,26.14 27.84,26.53
  L04_SIG2 w0.157: v2(14.55,39.19) 14.84,39.48 14.84,41.32 14.55,41.61 14.55,47.19 14.83,47.47 17.47,47.47 v2(17.75,47.18)
  BOTTOM w0.15: U2.3 28.82,23.04 28.97,23.19 28.97,23.47 v2(28.95,23.49)
PE84_SWCLK: length 54.5
  TOP w0.15: J4.4 13.39,44.73 13.58,44.93 15.06,44.93 15.95,44.04 15.95,41.85 16.57,41.23 16.81,41.23 v2(17.09,40.94) ; U1.R6 v1(23.19,27.41)
  L03_SIG1 w0.089: v1(23.19,27.41) 23.19,27.06 22.77,26.64 22.71,26.64 22.67,26.59
  L03_SIG1 w0.157: 22.67,26.59 21.98,25.91 21.98,25.27 21.77,25.05 21.77,24.76 21.59,24.58 21.59,23.16 20.71,22.29 v2(19.56,22.29)
  L04_SIG2 w0.157: v2(19.56,22.29) 19.56,22.18 19.18,21.79 18.06,21.79 17.53,22.32 10.05,22.32 8.75,23.62 8.75,25.25 9.5,26 9.5,31.24 11,32.74 11,33.28 14.8,37.08 14.83,37.08 15.4,37.65 16.35,37.65 17.91,39.2 17.91,40.13 17.38,40.66 v2(17.09,40.94)
  BOTTOM w0.15: v2(17.09,40.94) 17.73,41.58 17.73,43.39 17.22,43.9 R200.2 ; U2.47 19.72,22.24 19.69,22.28 19.57,22.28 v2(19.56,22.29)
PE84_SWDIO: length 50.9
  TOP w0.15: v2(17.78,40.92) 17.4,40.54 16.84,40.54 15.65,41.73 15.01,41.73 14.66,42.09 J4.2 ; U1.P6 v1(23.27,28.14)
  L03_SIG1 w0.089: v1(23.27,28.14) 22.83,27.7 22.83,27.13 22.3,26.59
  L03_SIG1 w0.157: 22.3,26.59 21.73,26.02 21.73,25.37 21.51,25.16 21.51,24.87 19.33,22.68 19.17,22.68 19.01,22.53 19.01,22.42 19.01,22.41 v2(19.01,22.22)
  L04_SIG2 w0.157: v2(17.78,40.92) 18.26,40.44 18.26,39.19 11.31,32.24 10.94,32.24 9.91,31.21 9.91,26.04 9.01,25.14 9.01,23.73 10.16,22.58 17.78,22.58 18.19,22.18 18.97,22.18 v2(19.01,22.22)
  BOTTOM w0.15: R199.2 20.88,40.97 20.19,41.66 18.52,41.66 v2(17.78,40.92) ; U2.46 19.72,21.84 19.68,21.88 19.35,21.88 v2(19.01,22.22)
PE84_SWO: length 28.8
  TOP w0.15: v2(16.66,39.73) 16.36,40.03 14.25,40.03 12.88,41.4 12.29,41.4 12.12,41.58 J4.6 ; U1.M6 v1(23.27,29.44)
  L03_SIG1 w0.089: v1(23.27,29.44) 23.61,29.78 23.61,30.79 23.36,31.03 22.47,31.03 22.29,31.21 22.29,32.26 22.06,32.49 20.07,32.49
  L03_SIG1 w0.157: 20.07,32.49 17.55,35 17.55,38.63 16.95,39.23 16.95,39.44 v2(16.66,39.73)
  BOTTOM w0.15: R201.2 16.38,43.74 15.04,42.39 15.04,40.18 15.19,40.03 16.36,40.03 v2(16.66,39.73)
PE84_TDI: length 28.5
  TOP w0.15: U1.N6 v1(23.27,28.79) ; v2(15.82,39.22) 15.26,39.78 14.15,39.78 12.85,41.07 11.07,41.07 10.85,41.3 J4.8
  L03_SIG1 w0.089: 21.18,30.58 22.54,30.58 22.93,30.19 22.93,29.3 22.94,29.29 22.94,29.12 v1(23.27,28.79)
  L03_SIG1 w0.157: v2(15.82,39.22) 15.82,38.74 17.03,37.53 17.03,34.73 21.18,30.58
  BOTTOM w0.15: v2(15.82,39.22) 15.34,39.22 14.76,39.8 14.76,41.13 14.76,41.13 14.76,41.47 14.76,41.47 14.76,42.55 15.57,43.36 R202.2
PE84_USB_CC1: length 18.9
  TOP w0.15: v2(8.82,7.67) 8.87,7.67 9.08,7.46 J2.A5 9.08,4.84 9.48,4.44 14.62,4.44 15.42,5.23 15.42,7.67 14.91,8.17 U21.1
  BOTTOM w0.15: U36.1 9.34,3.54 8.82,4.06 v2(8.82,7.67)
PE84_USB_CC2: length 11.4
  TOP w0.15: v2(12.24,8.11) 12.08,7.95 J2.B5 ; U21.2 15.31,8.49 v2(15.39,8.41)
  BOTTOM w0.15: U36.2 11.12,4.34 12.01,5.23 12.01,7.88 v2(12.24,8.11) 12.73,8.11 13.08,8.46 14.94,8.46 14.99,8.41 v2(15.39,8.41)
PE84_USB_CF: length 30.5
  TOP w0.15: v2(17.06,13.27) 17.06,12.86 17.09,12.83 17.09,12.78 17.09,12.78 TP3.1 17.11,11.87 R2.2 17.11,11.04 16.7,10.63 U21.6 ; U1.K8 v1(25.22,30.74)
  L03_SIG1 w0.157: v2(21.02,20.83) 21.51,20.34 21.51,18.95 21.35,18.8 20.4,18.8 19.53,19.67 17.28,19.67 16.76,19.15 16.76,16.23 16.87,16.13 16.87,14.55 16.31,13.99 16.31,13.84 16.3,13.84 16.3,13.5 16.31,13.49 16.31,13.42 16.47,13.26 16.64,13.26 16.65,13.27 v2(17.06,13.27)
  L04_SIG2 w0.089: v1(25.22,30.74) 24.87,30.38 24.87,28.93 24.86,28.93 24.86,27.58
  L04_SIG2 w0.102: 24.86,27.58 24.86,26.61 24.13,25.88 24.13,24.64 24.31,24.45 24.31,23.69 23.91,23.28
  L04_SIG2 w0.157: 23.91,23.28 21.45,20.83 v2(21.02,20.83)
PE84_USB_DIR: length 45.2
  TOP w0.15: U1.M5 22.61,29.43 v1(22.61,29.43) ; U21.11 13.81,9.83 13.76,9.78 R6.2 13.41,10.01 13.23,10.19 12.34,10.19 12.31,10.16 TP5.1 10.59,11.33 5.4,11.33 5.23,11.5 5.23,14.81 6.55,16.13 v2(6.55,18.92)
  L04_SIG2 w0.089: v1(22.61,29.43) 22.93,29.11 23.4,29.11 23.59,28.92 23.59,28.65 23.4,28.46 23.13,28.46 22.94,28.27 22.94,28 22.75,27.81 22.45,27.81 22.15,27.51 22.15,26.46
  L04_SIG2 w0.102: 22.15,26.46 22.15,25.26 22.01,25.12 22.01,23.28
  L04_SIG2 w0.157: v2(6.55,18.92) 6.96,18.92 7.11,18.77 7.44,18.77 8.28,19.61 9.67,19.61 10.43,18.85 11.1,18.85 11.79,19.54 11.79,20.1 11.79,20.21 12.33,20.75 17.03,20.75 17.29,20.48 19.72,20.48 22.01,22.77 22.01,23.28
PE84_USB_DM: length 46.7
  TOP w0.114: U1.P7 23.94,28.15 23.89,28.15 v1(23.86,28.13) ; J2.B7 9.55,6.73 9.55,7.71 v2(9.58,7.74) ; J2.A7 10.58,5.97 10.49,5.88 10.49,5.28 v2(10.7,5.07)
  L03_SIG1 w0.089: v1(23.86,28.13) 24.02,28.13 24.11,28.04 24.11,27.67 24.11,27.67 24.11,26.94 23.88,26.72 23.88,26.71 23.87,26.69 23.87,26.62 23.86,26.61 23.86,26.59
  L03_SIG1 w0.114: v2(10.7,5.07) 10.54,4.91 10.54,4.64 10.14,4.25 9.43,4.25 9.17,4.51 9.17,5.98 10.19,6.99 10.19,7.63 10.08,7.74 ; 10.08,7.74 10.19,7.85 10.19,8.36 10.56,8.73 11.17,8.73 12.03,9.59 12.32,9.59 12.45,9.72 12.8,9.72 12.93,9.59 13.49,9.59 13.62,9.72 13.96,9.72 14.1,9.59 14.44,9.59 14.58,9.72 14.92,9.72 15.05,9.59 15.4,9.59 15.53,9.72 15.87,9.72 16.01,9.59 16.52,9.59 17.29,8.82 22.03,8.82 22.28,9.07 23.45,9.07 24.16,9.78 24.16,11.72 24.02,11.86 24.02,12.2 24.16,12.33 24.16,12.68 23.93,12.9 23.93,13.46 23.63,13.77 23.63,22.99 24.11,23.47 24.18,23.55 24.18,24.16 23.86,24.48 23.86,26.59 ; 10.08,7.74 v2(9.58,7.74)
  BOTTOM w0.114: v2(9.58,7.74) 10.07,7.74 10.21,7.6 10.21,7.33 U30.1
PE84_USB_DP: length 46.6
  TOP w0.114: J2.B6 11.08,7.71 v2(11.05,7.74) ; U1.N7 23.93,28.79 v1(23.93,28.78) ; J2.A6 10.08,5.97 10.26,5.79 10.26,5.17 10.14,5.05 9.98,5.05 v2(9.96,5.07)
  L03_SIG1 w0.089: v1(23.93,28.78) 24.33,28.37 24.33,28.13 24.33,28.13 24.33,27.58 24.33,27.57 24.33,26.85 24.11,26.62 24.11,26.59
  L03_SIG1 w0.114: 10.55,7.74 10.44,7.63 10.44,6.89 10.11,6.55 10.11,6.39 10.19,6.31 10.19,6.15 10.02,5.99 9.86,5.99 9.78,6.07 9.62,6.07 9.42,5.87 9.42,4.61 9.54,4.5 10.04,4.5 10.29,4.75 10.29,4.96 10.18,5.07 v2(9.96,5.07) ; 10.55,7.74 10.44,7.86 10.44,8.26 10.67,8.48 11.27,8.48 12.13,9.34 16.42,9.34 17.19,8.57 22.13,8.57 22.39,8.82 23.55,8.82 24.4,9.68 24.4,12.78 24.18,13 24.18,13.56 23.88,13.87 23.88,22.89 24.36,23.37 24.43,23.44 24.43,24.26 24.11,24.59 24.11,26.59 ; 10.55,7.74 v2(11.05,7.74)
  BOTTOM w0.114: v2(11.05,7.74) 10.55,7.74 10.44,7.63 10.44,7.35 U30.2
PE84_USB_ID: length 43.2
  TOP w0.15: U21.9 14.21,10.63 14,10.84 13.54,10.84 13.43,10.95 R9.2 13.43,13.39 TP7.1 11.58,15.24 v2(10.21,15.24) 8.94,16.51 7.34,16.51 6.86,16.99 6.86,18.36 7.28,18.78 v2(7.28,19.19) ; U31.1 13.95,15.27 14.1,15.42 v2(14.5,15.42) ; U1.N5 v1(22.62,28.79)
  L03_SIG1 w0.157: v2(10.21,15.24) 13.92,15.24 14.09,15.42 v2(14.5,15.42)
  L04_SIG2 w0.089: v1(22.62,28.79) 22.28,28.44 22.28,27.97 21.92,27.61 21.92,26.49
  L04_SIG2 w0.102: 21.92,26.49 21.92,25.32 21.74,25.14 21.74,23.14
  L04_SIG2 w0.157: v2(7.28,19.19) 7.98,19.89 9.76,19.89 10.54,19.11 11,19.11 11.53,19.65 11.53,20.21 11.53,20.32 12.22,21.01 17.14,21.01 17.4,20.74 19.62,20.74 21.74,22.87 21.74,23.14
PE84_USB_OUT1: length 32.6
  TOP w0.15: U1.L4 v1(21.97,30.09) ; U21.7 15.31,11.9 R8.1 15.46,12.69 TP6.1 15.8,13.03 16.26,13.03 16.43,13.2 16.43,13.42 v2(16.71,13.71)
  L03_SIG1 w0.089: v1(21.97,30.09) 22.28,29.77 22.28,28.93 22.29,28.92 22.29,28.65 22.28,28.64 22.28,28.28 22.28,28.28 22.28,27.54 21.34,26.59
  L03_SIG1 w0.157: 21.34,26.59 20.62,25.88 20.62,24.74 19.33,23.45 18.44,23.45 18.01,23.01 18.01,22.15 18.69,21.46 21.26,21.46 21.91,20.82 21.91,18.86 21.58,18.54 20.29,18.54 19.43,19.41 17.55,19.41 17.02,18.88 17.02,16.64 17.79,15.87 17.79,14.8 17,14.01 17,14 v2(16.71,13.71)
PE84_USB_OUT2: length 33
  TOP w0.15: v2(15.93,13.46) 15.24,13.46 TP4.1 14.81,12.52 R5.1 14.81,11.69 14.91,11.59 U21.8 ; U1.N4 v1(21.97,28.79)
  L04_SIG2 w0.089: v1(21.97,28.79) 21.64,28.46 21.18,28.46 20.99,28.27 20.99,27.01 21.72,26.29
  L04_SIG2 w0.102: 21.72,26.29 21.72,25.4 21.54,25.23 21.54,23.3 21.48,23.25 21.48,22.98
  L04_SIG2 w0.157: v2(11.13,19.89) 11.13,20.78 11.66,21.31 17.37,21.31 17.68,21 19.51,21 21.48,22.98
  BOTTOM w0.15: v2(15.93,13.46) 15.77,13.46 15.44,13.79 15.44,14.17 14.91,14.71 14.91,15.76 14.84,15.83 14.41,16.26 12.88,16.26 11.68,17.45 11.68,19.33 v2(11.13,19.89)
PE84_VBUS: length 15.3
  TOP w0.178: C185.1 12.98,17.17 13.41,16.74 C1.2 13.49,16.74 13.89,17.14 U15.1
  TOP w0.229: R1.2 18.01,10.26 18.24,10.49 v3(18.24,10.72)
  L05_PWR w0.229: v3(18.24,15.83) 17.81,16.26 15.82,16.26 15.43,15.86 14.98,15.86 13.97,16.87 8.92,16.87 8.45,17.35 v3(7.98,17.35)
  BOTTOM w0.229: U26.6 15.86,17.71 16.14,17.99 C11.2
  vias: v3(7.32,17.35) v3(7.57,8.23) v3(7.95,7.72) v3(12.6,7.65) v3(13.17,7.87)
PE84_VCCD: length 40.4
  TOP w0.15: U1.M8 25.21,29.45 v1(25.21,29.4) ; U1.B1 v1(20.02,36.59) ; U1.H4 v1(21.97,32.04) ; U1.E9 v1(25.87,34.64) ; U1.B9 v1(25.87,36.59) ; U1.B12 v1(27.82,36.59) ; U1.F11 v1(27.17,33.99)
  L03_SIG1 w0.089: v1(25.87,34.64) 25.57,34.34 25.57,33.86 25.34,33.63 24.82,33.63 24.14,34.31 23.76,34.31 23.6,34.47 23.6,34.81 23.44,34.96 22.48,34.96 22.29,35.15 22.29,35.42 22.28,35.43 22.28,36.06 22.06,36.27 21.83,36.27 21.64,36.46 21.64,36.75 21.45,36.93 20.37,36.93 v1(20.02,36.59) ; 25.81,37.69 25.53,37.42 25.53,36.92 v1(25.87,36.59)
  L03_SIG1 w0.229: v3(25.53,40.9) 25.81,40.62 25.81,37.69
  L04_SIG2 w0.089: v1(25.87,34.64) 26.19,34.96 26.19,36.26 v1(25.87,36.59) ; 26.33,39.29 26.33,38.72 27.49,37.56 27.49,36.91 v1(27.82,36.59)
  L04_SIG2 w0.229: v3(25.53,40.9) 26.33,40.1 26.33,39.29
  L05_PWR w0.089: v1(25.21,29.4) 24.61,30 24.61,30.89 24.26,31.24 24.26,31.51 24.07,31.7 23.46,31.7 23.45,31.71 22.29,31.71 v1(21.97,32.04) 22.37,32.44 22.96,32.44 23.05,32.35 23.43,32.35 24.24,33.16 24.24,33.5 24.43,33.68 24.73,33.68 24.89,33.85 24.89,34.12 25.08,34.31 25.54,34.31 v1(25.87,34.64)
  BOTTOM w0.203: v1(27.17,33.99) 26.52,33.99 v1(25.87,34.64)
  BOTTOM w0.229: L5.2 27.07,39.64 27.43,40.01 C152.1 26.57,40.44 TP45.1 26.15,40.85 25.58,40.85 v3(25.53,40.9)
PE84_VDDA: length 13.5
  TOP w0.15: U1.J11 v1(27.17,31.39) ; U1.G12 v1(27.82,33.34) ; U1.L12 v1(27.82,30.09) ; U1.J12 v1(27.82,31.39) ; U1.H14 v1(29.12,32.04)
  L05_PWR w0.089: v3(31.07,32.18) 30.57,32.18 30.57,32.19 30.41,32.19 30.26,32.04 v1(29.12,32.04) 29.12,32.66 28.85,32.92 28.23,32.92 v1(27.82,33.34) U1.G12 27.49,31.71 v1(27.82,31.39) 28.14,31.06 28.14,30.41 v1(27.82,30.09) 27.49,30.41 27.49,30.87 27.17,31.19 v1(27.17,31.39)
  BOTTOM w0.229: FB9.2 31.47,31.6 31.07,32 v3(31.07,32.18) 31.06,32.19 C146.1
PE84_VTARG: length 134.5
  TOP w0.15: v3(17.5,18.75) 18.03,19.27 18.09,19.27 18.4,19.59 R32.2 R31.2 ; R198.1 8.39,23.24 v3(8.36,23.2) ; U1.B10 v1(26.52,36.59) ; C151.1 26.77,37.95 26.52,37.69 v1(26.52,37.24) U1.A10 ; v3(17.68,24.69) 17.68,24.09 17.57,23.98 16.52,23.98 16.16,23.62 14.45,23.62 14.05,23.22 12.62,23.22 12.02,23.82 12.02,24.02 11.91,24.13 R72.1 ; U1.D6 v1(23.27,35.29) ; U1.A11 v1(27.17,37.24)
  TOP w0.178: v3(8.36,23.2) 8.36,19.69 8.09,19.42 8.09,18.96 8.85,18.2 10.12,18.2 10.71,18.78 12.69,18.78 13.87,19.97 15.23,19.97 15.57,20.31 16.31,20.31 17.18,19.44 17.18,19.06 v3(17.5,18.75) ; v3(17.35,39.4) 17.35,39.84 17.82,40.31 FB10.2 ; R198.1 9.51,23.24 9.63,23.36 11.23,23.36 11.61,23.74 R72.1
  TOP w0.229: C54.1 v3(18.11,47.98) ; v3(17.17,45.39) 17.32,45.39 17.54,45.62 17.54,46.15 R196.1
  L03_SIG1 w0.152: v3(21.44,13.65) 21.44,16.07 19.74,17.78 19.74,18.59 19.28,19.05 18.23,19.05 17.93,18.75 v3(17.5,18.75)
  L04_SIG2 w0.15: 25.35,14.81 26.85,13.31 27.86,13.31 v3(28.44,13.88)
  L04_SIG2 w0.152: v3(21.44,13.65) 21.44,14.23 22.02,14.81 25.35,14.81
  L04_SIG2 w0.229: v3(17.17,45.39) 16.76,45.8 15.9,45.8 15.58,45.48 15.58,41.74 17.35,39.98 v3(17.35,39.4) 16.64,38.69 15.88,38.69 14.67,37.48 12.76,37.48 11.84,36.56 11.84,35 9.8,32.97 9.8,32.36 8.48,31.04 8.48,25.54 8.36,25.41 v3(8.36,23.2)
  L05_PWR w0.089: 20.07,36.01 20.71,36.01 20.96,36.26 21.43,36.26 21.44,36.25 22.09,36.25 22.28,36.06 22.28,35.79 22.46,35.61 22.94,35.61 v1(23.27,35.29) 23.59,35.61 23.59,36.06 23.4,36.25 23.14,36.25 22.94,36.45 22.94,36.72 22.75,36.91 22.11,36.91 22.1,36.92 21.74,36.92 21.58,37.08
  L05_PWR w0.152: 20.75,37.26 20.96,37.26 21.15,37.08 21.58,37.08 ; 20.71,36.01 20.71,36 19.98,36
  L05_PWR w0.229: v3(18.26,34.85) 17.93,34.52 17.93,31.7 18.71,30.92 18.71,29.24 19.18,28.78 19.18,27.97 18.9,27.69 18.9,26.11 19.11,25.89 19.11,25.57 18.91,25.36 18.91,24.63 19.46,24.08 20.24,24.08 20.6,24.44 24.88,24.44 25.09,24.65 27.25,24.65 27.76,24.14 28.86,24.14 28.94,24.21 v3(29.41,24.21)
  BOTTOM w0.15: v3(28.44,13.88) 28.01,14.31 R29.2 ; R21.1 18.01,24.17 17.98,24.2 17.98,24.39 v3(17.68,24.69) ; R23.1 20.9,14.66 21.44,14.12 v3(21.44,13.65)
  BOTTOM w0.229: FB11.2 18.49,34.49 18.26,34.72 v3(18.26,34.85) ; R202.1 R201.1 R200.1 17.22,45.34 v3(17.17,45.39) 17.17,45.86 18.31,47 18.31,47.78 v3(18.11,47.98) ; v1(27.17,37.24) v1(26.52,37.24) 26.01,37.74 C138.1 25.98,38.55 25.06,38.55 C150.1 24.68,38.93 24.51,38.93 23.99,39.45 FB8.1 23.65,40.51 23.37,40.79 v3(23.37,41.25) 22.99,41.25 22.71,40.97 R199.1
  BOTTOM w0.305: v3(29.41,24.21) 29.45,24.25 R226.1
PSEN_INT: length 33.8
  TOP w0.15: U1.E10 26.52,34.64 v1(26.54,34.64) ; v2(32.69,17.17) 32.69,18.47 U6.5 ; v2(30.66,33.88) 31.14,34.37 31.88,34.37 32.46,33.78 32.46,31.78 33.12,31.12 33.12,29.95 33.34,29.73 33.34,28.34 33.56,28.12 34.55,28.12 34.91,27.76 34.91,24.46 34.08,23.63 32.39,23.63 31.88,23.12 v2(31.88,22.71)
  L03_SIG1 w0.089: v1(26.54,34.64) 26.54,33.3 27.05,32.79 28.59,32.79 28.7,32.91 29.77,32.91 30.39,33.53 30.39,33.62 v2(30.66,33.88)
  BOTTOM w0.15: v2(31.88,22.71) 31.88,20.25 32.28,19.84 32.28,17.58 v2(32.69,17.17) 32.69,17.58 32.67,17.6 32.67,18.32 32.72,18.36 32.72,18.37 33.07,18.73 R84.1
